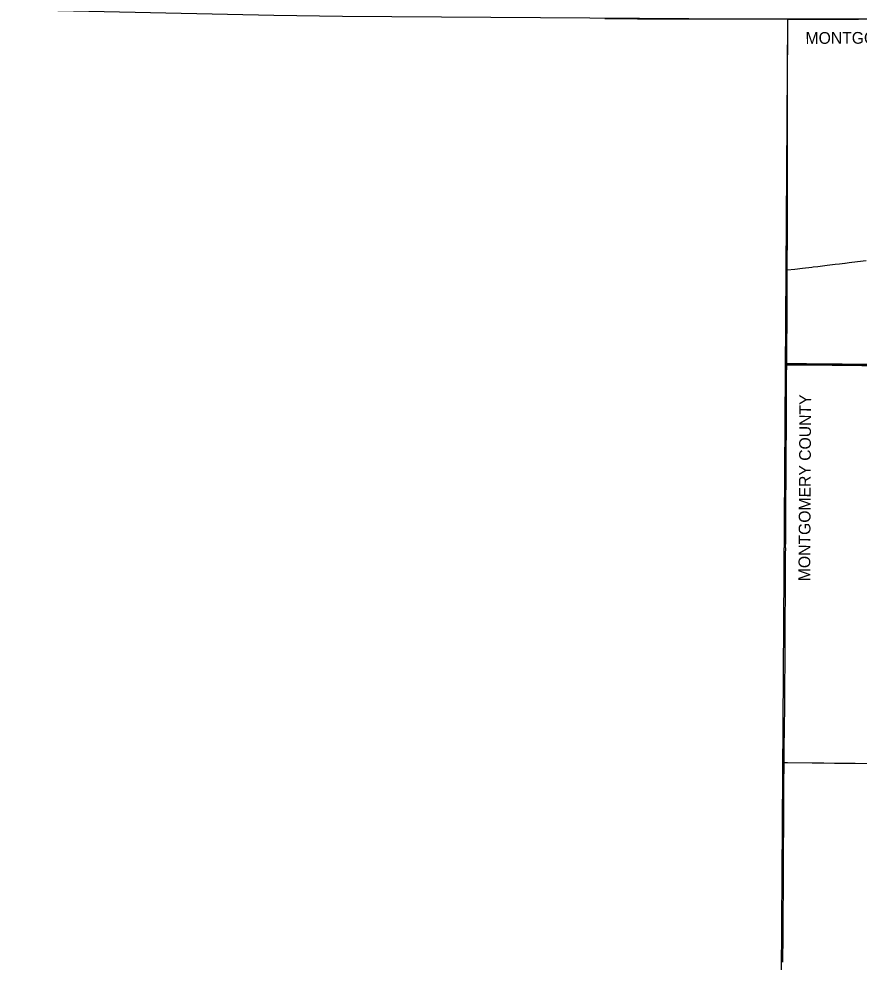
# Model space of a CAD drawing. Extents: x 0 to 34, y 0 to 22.
# Drawn here: x 2.941 to 4.091, y 14.836 to 16.127 of the extents above; entities that cross this region are included whole.
import ezdxf

# ---------------------------------------------------------------- set-up
doc = ezdxf.new("R2010")
doc.units = 0
for name, color, linetype in [('GM_X_County', 7, 'Continuous'), ('GM_X_County_Text', 7, 'Continuous'), ('GM_X_Interstate_Route', 7, 'Continuous'), ('GM_X_US_Route', 7, 'Continuous'), ('SC_Scratch1', 7, 'Continuous')]:
    doc.layers.add(name, color=color, linetype=linetype)

msp = doc.modelspace()

# ---------------------------------------------------------------- linework, layer by layer
at = {"layer": 'GM_X_County'}
for points in [[(4.1698, 16.1267), (4.0899, 16.1265), (4.0845, 16.1264), (4.0792, 16.1264), (4.0572, 16.1263), (4.054, 16.1263), (4.0478, 16.1263), (4.039, 16.1262), (4.0377, 16.1262), (4.0054, 16.1261), (3.9931, 16.1261), (3.992, 16.1261), (3.987, 16.1261), (3.9819, 16.1261), (3.9747, 16.1261), (3.9668, 16.1261), (3.9629, 16.1261), (3.9585, 16.1261), (3.9549, 16.1261), (3.9514, 16.1261), (3.9497, 16.1261), (3.9468, 16.1261), (3.9435, 16.1261), (3.941, 16.1261), (3.9368, 16.1261), (3.9341, 16.1261), (3.9315, 16.1261), (3.9294, 16.1261), (3.9231, 16.1261), (3.9181, 16.1261), (3.9129, 16.1261), (3.9079, 16.1261), (3.9055, 16.1261), (3.9017, 16.1261), (3.8974, 16.1262), (3.8938, 16.1262), (3.8903, 16.1262), (3.8871, 16.1262), (3.8837, 16.1262), (3.8802, 16.1262), (3.8773, 16.1262), (3.8757, 16.1262), (3.8727, 16.1263), (3.8689, 16.1263), (3.8683, 16.1263), (3.8678, 16.1263), (3.8675, 16.1263), (3.8668, 16.1263), (3.8658, 16.1263), (3.8658, 16.1263), (3.865, 16.1262), (3.8641, 16.1262), (3.8632, 16.1262), (3.8619, 16.1262), (3.8601, 16.1262), (3.8551, 16.1262), (3.8505, 16.1262), (3.8468, 16.1262), (3.8435, 16.1262), (3.8389, 16.1263), (3.833, 16.1263), (3.8293, 16.1263), (3.8228, 16.1264), (3.814, 16.1264), (3.8047, 16.1265), (3.7985, 16.1265), (3.7937, 16.1265), (3.7875, 16.1265), (3.7819, 16.1266), (3.7761, 16.1266), (3.7707, 16.1267), (3.7643, 16.1267), (3.7587, 16.1267), (3.7529, 16.1267), (3.7486, 16.1267), (3.7429, 16.1268)], [(3.9864, 14.8354), (3.9864, 14.8363), (3.9864, 14.8371), (3.9864, 14.8385), (3.9865, 14.8403), (3.9865, 14.8413), (3.9865, 14.8445), (3.9866, 14.848), (3.9866, 14.8504), (3.9866, 14.8523), (3.9866, 14.8525), (3.9866, 14.853), (3.9867, 14.8548), (3.9867, 14.8566), (3.9867, 14.858), (3.9867, 14.8592), (3.9868, 14.8606), (3.9868, 14.8615), (3.9868, 14.862), (3.9868, 14.8647), (3.9868, 14.8658), (3.9868, 14.8681), (3.9869, 14.8695), (3.9869, 14.8715), (3.9869, 14.8752), (3.9869, 14.8782), (3.9869, 14.8818), (3.9869, 14.8828), (3.9869, 14.8841), (3.9869, 14.8861), (3.9869, 14.8877), (3.9869, 14.8894), (3.9869, 14.8903), (3.9869, 14.8915), (3.9869, 14.8931), (3.9869, 14.8946), (3.9869, 14.895), (3.9869, 14.8978), (3.9869, 14.8987), (3.987, 14.9005), (3.987, 14.9018), (3.987, 14.903), (3.987, 14.9042), (3.987, 14.9054), (3.987, 14.9066), (3.987, 14.9072), (3.987, 14.9087), (3.987, 14.9104), (3.987, 14.9127), (3.987, 14.9152), (3.987, 14.9174), (3.9871, 14.9223), (3.9871, 14.9235), (3.9871, 14.9251), (3.9871, 14.927), (3.9872, 14.9292), (3.9872, 14.9317), (3.9872, 14.9326), (3.9872, 14.9341), (3.9872, 14.9354), (3.9872, 14.9365), (3.9872, 14.9389), (3.9872, 14.9397), (3.9872, 14.9414), (3.9872, 14.9426), (3.9872, 14.9434), (3.9872, 14.9449), (3.9872, 14.9461), (3.9872, 14.947), (3.9873, 14.9488), (3.9873, 14.9506), (3.9873, 14.9521), (3.9873, 14.953), (3.9873, 14.9542), (3.9873, 14.9554), (3.9873, 14.9571), (3.9873, 14.9591), (3.9873, 14.9599), (3.9873, 14.962), (3.9873, 14.9638), (3.9873, 14.9643), (3.9873, 14.9653), (3.9873, 14.9671), (3.9874, 14.9683), (3.9874, 14.9698), (3.9874, 14.971), (3.9874, 14.9722), (3.9874, 14.9734), (3.9874, 14.9744), (3.9874, 14.9756), (3.9874, 14.9767), (3.9874, 14.9777), (3.9874, 14.9787), (3.9874, 14.9797), (3.9874, 14.9798), (3.9874, 14.98), (3.9874, 14.9802), (3.9874, 14.9811), (3.9874, 14.9818), (3.9874, 14.9845), (3.9874, 14.9862), (3.9874, 14.9879), (3.9874, 14.9891), (3.9874, 14.9913), (3.9874, 14.9927), (3.9874, 14.9957), (3.9874, 14.9969), (3.9875, 14.9986), (3.9875, 14.9998), (3.9875, 15.0005), (3.9875, 15.0025), (3.9875, 15.0038), (3.9875, 15.0047), (3.9876, 15.0065), (3.9876, 15.0081), (3.9876, 15.0092), (3.9876, 15.011), (3.9876, 15.0127), (3.9876, 15.0139), (3.9876, 15.0154), (3.9876, 15.0164), (3.9876, 15.0186), (3.9877, 15.0206), (3.9877, 15.022), (3.9876, 15.0239), (3.9876, 15.0255), (3.9876, 15.0283), (3.9876, 15.0304), (3.9876, 15.0313), (3.9876, 15.0333), (3.9876, 15.035), (3.9876, 15.0361), (3.9876, 15.0382), (3.9876, 15.0394), (3.9876, 15.0425), (3.9876, 15.0434), (3.9877, 15.0453), (3.9877, 15.0471), (3.9877, 15.0518), (3.9877, 15.0532), (3.9877, 15.0546), (3.9877, 15.0558), (3.9877, 15.0568), (3.9877, 15.0586), (3.9877, 15.0598), (3.9878, 15.0605), (3.9878, 15.0633), (3.9878, 15.065), (3.9878, 15.0658), (3.9878, 15.0677), (3.9878, 15.0699), (3.9878, 15.0738), (3.9878, 15.0747), (3.9878, 15.0757), (3.9878, 15.0764), (3.9878, 15.0772), (3.9878, 15.079), (3.9878, 15.0803), (3.9878, 15.0815), (3.9879, 15.0838), (3.9879, 15.0859), (3.9879, 15.0875), (3.9879, 15.089), (3.9879, 15.0905), (3.988, 15.0952), (3.988, 15.0988), (3.988, 15.1041), (3.988, 15.106), (3.988, 15.1073), (3.988, 15.109), (3.988, 15.1101), (3.988, 15.1114), (3.988, 15.1128), (3.9881, 15.1142), (3.9881, 15.1163), (3.9881, 15.1173), (3.9881, 15.12), (3.9882, 15.124), (3.9882, 15.1247), (3.9882, 15.1265), (3.9882, 15.1279), (3.9882, 15.1291), (3.9883, 15.1339), (3.9884, 15.1388), (3.9884, 15.1405), (3.9884, 15.1421), (3.9885, 15.1435), (3.9885, 15.1461), (3.9885, 15.1469), (3.9886, 15.149), (3.9886, 15.1508), (3.9886, 15.155), (3.9887, 15.1563), (3.9887, 15.1582), (3.9888, 15.1621), (3.9888, 15.1671), (3.9888, 15.1701), (3.9889, 15.1718), (3.9889, 15.1742), (3.9889, 15.1765), (3.9889, 15.1773), (3.9889, 15.1819), (3.989, 15.1846), (3.989, 15.1868), (3.989, 15.1895), (3.989, 15.1906), (3.989, 15.1933), (3.989, 15.1938), (3.9891, 15.1946), (3.9891, 15.1955), (3.9891, 15.198), (3.9891, 15.1994), (3.9891, 15.2004), (3.9892, 15.2023), (3.9892, 15.2042), (3.9892, 15.2059), (3.9892, 15.2076), (3.9892, 15.2086), (3.9892, 15.2106), (3.9892, 15.212), (3.9893, 15.2142), (3.9893, 15.2148), (3.9893, 15.2168), (3.9893, 15.2185), (3.9893, 15.2212), (3.9893, 15.2232), (3.9893, 15.228), (3.9894, 15.2324), (3.9894, 15.2366), (3.9894, 15.2414), (3.9894, 15.2433), (3.9895, 15.2454), (3.9895, 15.2465), (3.9895, 15.2506), (3.9895, 15.252), (3.9895, 15.2539), (3.9895, 15.2556), (3.9895, 15.2574), (3.9896, 15.2589), (3.9896, 15.2596), (3.9896, 15.2629), (3.9896, 15.2664), (3.9896, 15.2713), (3.9897, 15.2735), (3.9897, 15.2751), (3.9897, 15.2776), (3.9897, 15.2793), (3.9897, 15.2799), (3.9897, 15.2816), (3.9897, 15.2833), (3.9897, 15.2846), (3.9897, 15.2859), (3.9897, 15.2897), (3.9897, 15.2912), (3.9897, 15.2931), (3.9897, 15.2959), (3.9898, 15.2978), (3.9898, 15.2997), (3.9898, 15.3019), (3.9898, 15.3034), (3.9898, 15.3053), (3.9898, 15.3065), (3.9898, 15.3093), (3.9898, 15.311), (3.9898, 15.315), (3.9898, 15.3169), (3.9898, 15.3177), (3.9898, 15.3192), (3.9898, 15.3212), (3.9899, 15.323), (3.9899, 15.3264), (3.9899, 15.3301), (3.9899, 15.3323), (3.9899, 15.3336), (3.9899, 15.3348), (3.9899, 15.3381), (3.9899, 15.3403), (3.9899, 15.3422), (3.9899, 15.3441), (3.99, 15.3467), (3.99, 15.3489), (3.99, 15.3506), (3.99, 15.352), (3.99, 15.3532), (3.99, 15.3552), (3.99, 15.3596), (3.99, 15.361), (3.99, 15.3633), (3.99, 15.3636), (3.99, 15.3647), (3.99, 15.3671), (3.99, 15.3687), (3.99, 15.3708), (3.99, 15.372), (3.9901, 15.3729), (3.9901, 15.3752), (3.9901, 15.3802), (3.9901, 15.3823), (3.9901, 15.3843), (3.9902, 15.3857), (3.9902, 15.3878), (3.9902, 15.3895), (3.9902, 15.3912), (3.9902, 15.3924), (3.9902, 15.3935), (3.9902, 15.3967), (3.9903, 15.3998), (3.9903, 15.4012), (3.9903, 15.4021), (3.9903, 15.4024), (3.9903, 15.4026), (3.9902, 15.4029), (3.9902, 15.4031), (3.9902, 15.4036), (3.9902, 15.4043), (3.9902, 15.4045), (3.9902, 15.4055), (3.9902, 15.4062), (3.9902, 15.4073), (3.9903, 15.4088), (3.9903, 15.4116), (3.9903, 15.4138), (3.9903, 15.4164), (3.9903, 15.4191), (3.9904, 15.4225), (3.9904, 15.4244), (3.9904, 15.4261), (3.9904, 15.4295), (3.9905, 15.4308), (3.9905, 15.4316), (3.9905, 15.4339), (3.9905, 15.4361), (3.9905, 15.438), (3.9905, 15.4421), (3.9905, 15.4452), (3.9906, 15.4489), (3.9906, 15.4512), (3.9906, 15.4527), (3.9906, 15.4576), (3.9906, 15.4593), (3.9906, 15.4604), (3.9907, 15.4623), (3.9907, 15.4651), (3.9907, 15.4672), (3.9907, 15.4701), (3.9907, 15.4717), (3.9907, 15.473), (3.9907, 15.4751), (3.9907, 15.4777), (3.9907, 15.4806), (3.9908, 15.4828), (3.9908, 15.4845), (3.9908, 15.4858), (3.9908, 15.4875), (3.9908, 15.4887), (3.9908, 15.4904), (3.9908, 15.4908), (3.9908, 15.4912), (3.9908, 15.4914), (3.9908, 15.4918), (3.9908, 15.4922), (3.9908, 15.494), (3.9909, 15.497), (3.9909, 15.4982), (3.9909, 15.5032), (3.9909, 15.5054), (3.9909, 15.5073), (3.9909, 15.5096), (3.9909, 15.5113), (3.9909, 15.5124), (3.9909, 15.5142), (3.9909, 15.5161), (3.991, 15.5175), (3.991, 15.5195), (3.991, 15.5216), (3.991, 15.5248), (3.991, 15.5271), (3.991, 15.5291), (3.991, 15.5304), (3.991, 15.5331), (3.9911, 15.5335), (3.9911, 15.5351), (3.9911, 15.5356), (3.9911, 15.5367), (3.9911, 15.5386), (3.9911, 15.54), (3.9911, 15.5421), (3.9911, 15.5454), (3.9911, 15.5488), (3.9912, 15.5508), (3.9912, 15.5527), (3.9912, 15.5553), (3.9912, 15.5581), (3.9912, 15.5614), (3.9913, 15.5632), (3.9913, 15.5651), (3.9913, 15.5677), (3.9913, 15.5702), (3.9913, 15.572), (3.9913, 15.5739), (3.9913, 15.5765), (3.9914, 15.5793), (3.9914, 15.5824), (3.9914, 15.5848), (3.9914, 15.588), (3.9914, 15.5908), (3.9914, 15.5916), (3.9914, 15.5927), (3.9914, 15.5952), (3.9914, 15.5972), (3.9914, 15.6005), (3.9914, 15.6035), (3.9914, 15.6053), (3.9914, 15.6079), (3.9914, 15.6097), (3.9914, 15.6102), (3.9914, 15.6107), (3.9915, 15.6126), (3.9915, 15.6158), (3.9915, 15.6179), (3.9915, 15.6201), (3.9915, 15.6228), (3.9915, 15.6254), (3.9916, 15.6279), (3.9916, 15.63), (3.9916, 15.631), (3.9916, 15.633), (3.9916, 15.6345), (3.9916, 15.6356), (3.9916, 15.6371), (3.9916, 15.6387), (3.9916, 15.6405), (3.9916, 15.6428), (3.9916, 15.6443), (3.9917, 15.6472), (3.9917, 15.6491), (3.9917, 15.6505), (3.9917, 15.6526), (3.9917, 15.6534), (3.9917, 15.654), (3.9917, 15.6551), (3.9917, 15.6562), (3.9918, 15.658), (3.9918, 15.6596), (3.9918, 15.6611), (3.9918, 15.6623), (3.9918, 15.6639), (3.9918, 15.6665), (3.9918, 15.6679), (3.9918, 15.6688), (3.9918, 15.6699), (3.9919, 15.6723), (3.9919, 15.6754), (3.9919, 15.6789), (3.9919, 15.6809), (3.9919, 15.6836), (3.992, 15.6851), (3.992, 15.6866), (3.992, 15.6883), (3.992, 15.6896), (3.992, 15.6919), (3.992, 15.694), (3.992, 15.6948), (3.992, 15.6954), (3.992, 15.6957), (3.9921, 15.6965), (3.9921, 15.6971), (3.9921, 15.6984), (3.9921, 15.701), (3.9921, 15.7015), (3.9921, 15.704), (3.9921, 15.7052), (3.9921, 15.7087), (3.9921, 15.7108), (3.9921, 15.7123), (3.9921, 15.7148), (3.9921, 15.7188), (3.9921, 15.7212), (3.9922, 15.7242), (3.9922, 15.7265), (3.9922, 15.7292), (3.9922, 15.7313), (3.9922, 15.7334), (3.9922, 15.7351), (3.9922, 15.7364), (3.9923, 15.7397), (3.9923, 15.7427), (3.9923, 15.7451), (3.9923, 15.7466), (3.9923, 15.7483), (3.9923, 15.75), (3.9923, 15.7529), (3.9923, 15.7546), (3.9923, 15.7563), (3.9924, 15.7575), (3.9924, 15.7598), (3.9924, 15.7616), (3.9924, 15.7628), (3.9924, 15.7656), (3.9924, 15.768), (3.9924, 15.7712), (3.9925, 15.7737), (3.9925, 15.7771), (3.9925, 15.779), (3.9924, 15.7815), (3.9924, 15.7819), (3.9924, 15.7822), (3.9925, 15.7823), (3.9925, 15.7824), (3.9925, 15.7825), (3.9925, 15.7826), (3.9925, 15.7828), (3.9925, 15.783), (3.9925, 15.7833), (3.9925, 15.7835), (3.9925, 15.7839), (3.9925, 15.784), (3.9925, 15.7842), (3.9925, 15.7848), (3.9925, 15.788), (3.9925, 15.7905), (3.9925, 15.7937), (3.9925, 15.7956), (3.9925, 15.7983), (3.9925, 15.8008), (3.9925, 15.8026), (3.9925, 15.8048), (3.9925, 15.8089), (3.9926, 15.8105), (3.9926, 15.8121), (3.9926, 15.8144), (3.9926, 15.8168), (3.9926, 15.8178), (3.9926, 15.8203), (3.9926, 15.8237), (3.9926, 15.827), (3.9926, 15.8302), (3.9926, 15.8336), (3.9926, 15.836), (3.9926, 15.8387), (3.9926, 15.8394), (3.9927, 15.8424), (3.9927, 15.8456), (3.9926, 15.8505), (3.9926, 15.8533), (3.9927, 15.8572), (3.9927, 15.8606), (3.9927, 15.8611), (3.9927, 15.8636), (3.9927, 15.8654), (3.9927, 15.8664), (3.9927, 15.8669), (3.9927, 15.8704), (3.9927, 15.8718), (3.9927, 15.8751), (3.9927, 15.8782), (3.9927, 15.8826), (3.9928, 15.8842), (3.9928, 15.8872), (3.9928, 15.8894), (3.9928, 15.8913), (3.9928, 15.8945), (3.9928, 15.8978), (3.9928, 15.8993), (3.9928, 15.9012), (3.9928, 15.9028), (3.9928, 15.9053), (3.9928, 15.9071), (3.9928, 15.9094), (3.9928, 15.9133), (3.9928, 15.916), (3.9928, 15.9187), (3.9928, 15.9233), (3.9928, 15.9245), (3.9928, 15.9258), (3.9928, 15.9286), (3.9929, 15.9306), (3.9929, 15.9325), (3.9929, 15.9363), (3.9929, 15.9379), (3.9929, 15.9398), (3.9929, 15.9414), (3.9929, 15.9437), (3.9929, 15.9449), (3.9929, 15.9465), (3.9929, 15.9477), (3.9929, 15.9494), (3.9929, 15.9505), (3.9929, 15.9516), (3.9929, 15.9522), (3.9929, 15.9538), (3.9929, 15.9546), (3.9929, 15.9562), (3.9928, 15.9591), (3.9929, 15.9603), (3.9929, 15.9621), (3.9929, 15.9633), (3.9929, 15.9647), (3.9929, 15.9671), (3.9929, 15.9679), (3.9929, 15.9693), (3.9929, 15.9703), (3.9929, 15.9713), (3.9929, 15.9734), (3.9929, 15.9754), (3.9929, 15.9779), (3.9929, 15.9798), (3.9929, 15.9817), (3.9929, 15.9832), (3.9929, 15.9845), (3.9929, 15.9863), (3.9929, 15.9878), (3.9929, 15.9893), (3.9929, 15.991), (3.9929, 15.9928), (3.9929, 15.9941), (3.9929, 15.9969), (3.993, 15.9984), (3.993, 16.0001), (3.993, 16.0015), (3.993, 16.0031), (3.993, 16.0045), (3.993, 16.0057), (3.993, 16.0097), (3.993, 16.01), (3.993, 16.0125), (3.993, 16.0149), (3.993, 16.0179), (3.993, 16.0192), (3.993, 16.02), (3.993, 16.0241), (3.993, 16.0292), (3.993, 16.0311), (3.993, 16.0314), (3.993, 16.0321), (3.993, 16.0334), (3.993, 16.0341), (3.993, 16.0345), (3.993, 16.0348), (3.993, 16.036), (3.993, 16.0365), (3.993, 16.0368), (3.993, 16.0371), (3.993, 16.0373), (3.993, 16.0379), (3.993, 16.0383), (3.993, 16.0415), (3.993, 16.0426), (3.993, 16.0439), (3.993, 16.045), (3.993, 16.0456), (3.993, 16.0461), (3.993, 16.0467), (3.993, 16.0472), (3.993, 16.0481), (3.993, 16.0488), (3.993, 16.0493), (3.993, 16.0506), (3.993, 16.0539), (3.993, 16.0555), (3.993, 16.0575), (3.993, 16.0594), (3.993, 16.0609), (3.993, 16.0629), (3.993, 16.0642), (3.993, 16.0656), (3.993, 16.0666), (3.993, 16.0681), (3.993, 16.0691), (3.993, 16.0706), (3.993, 16.073), (3.993, 16.0739), (3.993, 16.0748), (3.993, 16.0758), (3.993, 16.0766), (3.993, 16.0773), (3.9931, 16.0777), (3.9931, 16.078), (3.9931, 16.0782), (3.9931, 16.1261), (4.0054, 16.1261), (4.0377, 16.1262), (4.039, 16.1262), (4.0478, 16.1263), (4.054, 16.1263), (4.0572, 16.1263), (4.0792, 16.1264), (4.0845, 16.1264), (4.0899, 16.1265), (4.1698, 16.1267)]]:
    msp.add_lwpolyline(points, dxfattribs=at)
at = {"layer": 'GM_X_Interstate_Route'}
for points in [[(3.9917, 15.655), (4.0054, 15.6549), (4.0188, 15.6548), (4.0326, 15.6547), (4.0539, 15.6545), (4.0678, 15.6544), (4.0803, 15.6543), (4.0819, 15.6543), (4.0851, 15.6543), (4.0944, 15.6542), (4.1151, 15.654), (4.1332, 15.6538), (4.1459, 15.6537), (4.1518, 15.6537), (4.1551, 15.6538), (4.1597, 15.6541), (4.1627, 15.6543), (4.1667, 15.6548), (4.1691, 15.6552)], [(3.9917, 15.6533), (4.0054, 15.6532), (4.0188, 15.6531), (4.0326, 15.653), (4.0539, 15.6528), (4.0678, 15.6527), (4.0803, 15.6525), (4.082, 15.6525), (4.0851, 15.6525), (4.0944, 15.6524), (4.115, 15.6523), (4.1331, 15.6521), (4.1459, 15.652), (4.1517, 15.6519), (4.1551, 15.652), (4.1597, 15.6523), (4.1627, 15.6526), (4.1667, 15.6531), (4.1688, 15.6534)]]:
    msp.add_lwpolyline(points, dxfattribs=at)
at = {"layer": 'GM_X_US_Route'}
msp.add_line((4.0778, 15.1079), (4.0852, 15.1078), dxfattribs=at)
for points in [[(4.0279, 15.7872), (4.0344, 15.788), (4.0471, 15.7895), (4.058, 15.7908), (4.0641, 15.7915), (4.0714, 15.7924)], [(4.0714, 15.7924), (4.0717, 15.7924), (4.0774, 15.7931), (4.0885, 15.7944), (4.1006, 15.7959)], [(3.9924, 15.783), (4.003, 15.7842), (4.0132, 15.7854), (4.0262, 15.787), (4.0279, 15.7872)], [(3.9881, 15.1089), (3.9927, 15.1088), (4.0267, 15.1084), (4.0381, 15.1083), (4.0424, 15.1083), (4.0573, 15.1081), (4.0778, 15.1079)], [(4.0852, 15.1078), (4.1036, 15.1076), (4.1184, 15.1074), (4.1504, 15.1071), (4.2068, 15.1065), (4.2399, 15.1062)]]:
    msp.add_lwpolyline(points, dxfattribs=at)
at = {"layer": 'SC_Scratch1'}
msp.add_lwpolyline([(3.9803, 14.1988), (3.9931, 16.126), (3.3837, 16.1299), (3.2897, 16.1315), (2.8882, 16.1402)], dxfattribs=at)

# ---------------------------------------------------------------- texts
at = {"layer": 'GM_X_County_Text'}
for rotation, p in [(0.1585, (4.0175, 16.0925)), (89.6828, (4.0238, 15.357))]:
    msp.add_text('MONTGOMERY COUNTY', height=0.016074, rotation=rotation, dxfattribs=at).set_placement(p)

doc.saveas('drawing.dxf')
